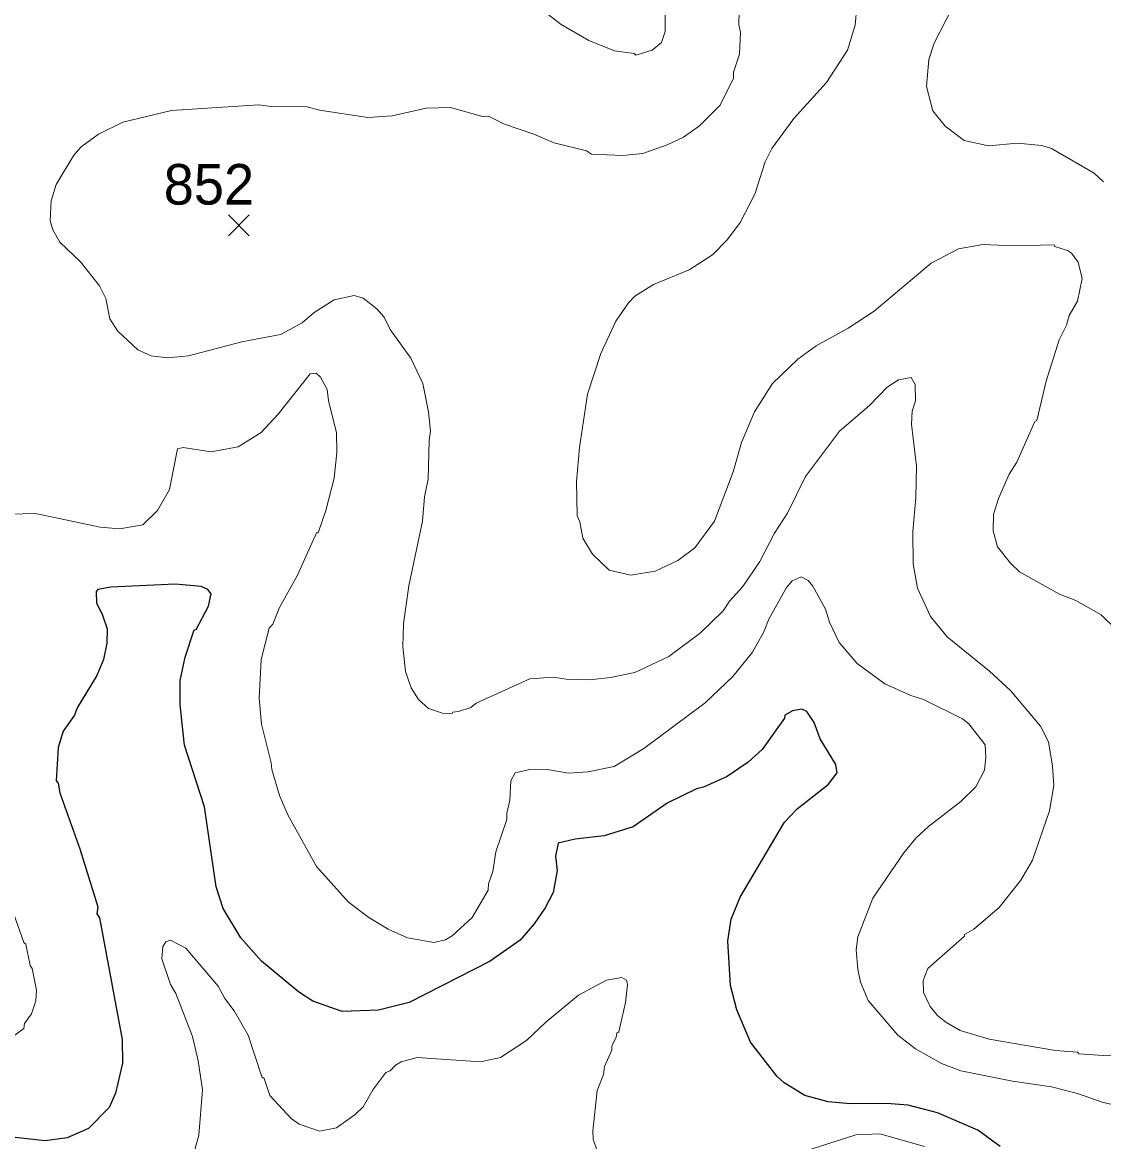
# Model space of a CAD drawing. Extents: x 265.7 to 292.1, y 7676.2 to 7704.2.
# Drawn here: x 273.408 to 275.542, y 7690.238 to 7692.446 of the extents above; entities that cross this region are included whole.
import ezdxf
from ezdxf.enums import TextEntityAlignment as Align

# ---------------------------------------------------------------- set-up
doc = ezdxf.new("R2010")
doc.units = 0
doc.header["$LTSCALE"] = 0.032
for name, color, linetype, lineweight in [('1', 7, 'Continuous', 25), ('2', 7, 'Continuous', 13), ('21', 7, 'Continuous', 25)]:
    doc.layers.add(name, color=color, linetype=linetype, lineweight=lineweight)
doc.layers.add('61', color=7, linetype='Continuous')

msp = doc.modelspace()

# ---------------------------------------------------------------- linework, layer by layer
at = {"layer": '1'}
for points in [[(275.3375, 7690.2284), (275.2936, 7690.2603), (275.2138, 7690.2946), (275.1564, 7690.3098), (275.1133, 7690.313), (275.0415, 7690.3122), (274.9984, 7690.3162), (274.9521, 7690.3289), (274.9114, 7690.3537), (274.8978, 7690.3664), (274.8451, 7690.4343), (274.818, 7690.4981), (274.8053, 7690.546), (274.8005, 7690.6338), (274.8068, 7690.6768), (274.8244, 7690.7199), (274.9122, 7690.8684), (274.9369, 7690.8947), (274.9984, 7690.9426), (275.0159, 7690.9657), (275.0135, 7690.9817), (274.9824, 7691.0327), (274.9704, 7691.0647), (274.9561, 7691.0862), (274.9465, 7691.091), (274.9281, 7691.0878), (274.913, 7691.079), (274.9122, 7691.0734), (274.8683, 7691.0112), (274.8404, 7690.9864), (274.7989, 7690.9585), (274.7526, 7690.937), (274.7382, 7690.9338), (274.6808, 7690.9058), (274.6138, 7690.8588), (274.5563, 7690.8412), (274.4988, 7690.8348), (274.4653, 7690.8268), (274.4605, 7690.8013), (274.4637, 7690.7726), (274.4557, 7690.7295), (274.4398, 7690.6992), (274.4182, 7690.6673), (274.3903, 7690.6353), (274.3313, 7690.5938), (274.1717, 7690.5125), (274.111, 7690.4973), (274.0392, 7690.4949), (273.9818, 7690.5148), (273.953, 7690.5332), (273.8804, 7690.5938), (273.8397, 7690.6401), (273.8046, 7690.6976), (273.791, 7690.7407), (273.7679, 7690.8987), (273.728, 7691.02), (273.72, 7691.0998), (273.72, 7691.1476), (273.7296, 7691.1939), (273.7472, 7691.2474), (273.7511, 7691.2482), (273.7759, 7691.2945), (273.7807, 7691.3184), (273.7743, 7691.3272), (273.7615, 7691.3328), (273.7105, 7691.3375), (273.5828, 7691.332), (273.5572, 7691.3272), (273.5541, 7691.3232), (273.5549, 7691.3)], [(273.5549, 7691.3), (273.566, 7691.2785), (273.5756, 7691.2498), (273.5748, 7691.2211), (273.5684, 7691.1891), (273.5556, 7691.1572), (273.5165, 7691.0934)], [(273.5165, 7691.0934), (273.511, 7691.079), (273.4886, 7691.0479), (273.479, 7691.0152), (273.4751, 7690.9497), (273.479, 7690.945), (273.4822, 7690.9258), (273.5221, 7690.8157), (273.5572, 7690.7008), (273.5556, 7690.6872), (273.5604, 7690.6792), (273.6051, 7690.4391), (273.6059, 7690.3928), (273.5923, 7690.3337), (273.5796, 7690.305), (273.5389, 7690.2635), (273.4966, 7690.2451), (273.4535, 7690.2395), (273.3099, 7690.2555)]]:
    msp.add_lwpolyline(points, dxfattribs=at)
at = {"layer": '2'}
for points in [[(274.6768, 7692.4659), (274.6768, 7692.4276), (274.6696, 7692.406), (274.6513, 7692.3909), (274.6185, 7692.3813), (274.6153, 7692.3845), (274.577, 7692.3901), (274.526, 7692.41), (274.4717, 7692.4419), (274.3265, 7692.5536)], [(274.8228, 7692.4675), (274.822, 7692.4419), (274.8252, 7692.426), (274.8236, 7692.3829), (274.8116, 7692.3478), (274.8116, 7692.3358), (274.7853, 7692.2823), (274.7446, 7692.2416), (274.7127, 7692.2193), (274.6808, 7692.2041), (274.6329, 7692.1874), (274.593, 7692.1834), (274.5316, 7692.1858), (274.5212, 7692.1922), (274.4574, 7692.2081), (274.4175, 7692.2257), (274.36, 7692.2448), (274.3281, 7692.2608), (274.3161, 7692.26), (274.2531, 7692.2783), (274.2052, 7692.2768), (274.1382, 7692.2616), (274.0903, 7692.2584), (273.9945, 7692.2728), (273.9706, 7692.2791), (273.8988, 7692.2799), (273.8748, 7692.2831), (273.7025, 7692.272), (273.6067, 7692.2488), (273.5588, 7692.2257), (273.5245, 7692.2001), (273.5102, 7692.1842), (273.4751, 7692.1259), (273.4655, 7692.094), (273.4631, 7692.0541), (273.4687, 7692.0366), (273.4822, 7692.0126), (273.5229, 7691.9735), (273.5604, 7691.9264), (273.5732, 7691.9009), (273.5812, 7691.861), (273.5963, 7691.8371), (273.6362, 7691.7996), (273.6626, 7691.7884), (273.6945, 7691.7844), (273.736, 7691.7884), (273.8413, 7691.8155), (273.9179, 7691.8299), (273.9602, 7691.853), (273.9842, 7691.8738)], [(275.055, 7692.477), (275.0518, 7692.4403), (275.0367, 7692.3909), (274.9952, 7692.327), (274.9305, 7692.256), (274.8874, 7692.197), (274.8739, 7692.1706), (274.8539, 7692.1068), (274.8244, 7692.0509), (274.7997, 7692.0174), (274.7701, 7691.9871), (274.7239, 7691.9576), (274.6537, 7691.9288), (274.6169, 7691.9057), (274.6042, 7691.8929), (274.5794, 7691.8562), (274.5499, 7691.7924), (274.5236, 7691.7126), (274.5076, 7691.6073), (274.502, 7691.5402), (274.5028, 7691.4724), (274.5084, 7691.4604), (274.514, 7691.4285), (274.5332, 7691.3966), (274.5659, 7691.3655), (274.609, 7691.3551), (274.6568, 7691.3631), (274.7015, 7691.3846), (274.735, 7691.4094), (274.7741, 7691.462), (274.8108, 7691.5594), (274.8276, 7691.6168), (274.8531, 7691.6775), (274.8882, 7691.7333), (274.9385, 7691.7812), (274.9744, 7691.8076), (275.0375, 7691.8427), (275.0893, 7691.8762), (275.2018, 7691.9711), (275.2553, 7691.9991), (275.3032, 7692.0078), (275.3638, 7692.0054), (275.4444, 7692.007), (275.4452, 7692.0038), (275.4708, 7691.9959), (275.4787, 7691.9903), (275.4915, 7691.9727), (275.4995, 7691.9408), (275.4899, 7691.8961), (275.4739, 7691.8674), (275.4684, 7691.8483), (275.454, 7691.8195), (275.4285, 7691.7381), (275.4101, 7691.6607), (275.4061, 7691.6583), (275.3702, 7691.5785)], [(275.2433, 7692.4754), (275.2074, 7692.4052), (275.1971, 7692.3725), (275.1923, 7692.3191), (275.205, 7692.2712), (275.229, 7692.2409), (275.2665, 7692.2129), (275.3144, 7692.2025), (275.3718, 7692.2073), (275.4197, 7692.2033), (275.4388, 7692.197), (275.5234, 7692.1483), (275.5418, 7692.1315)], [(273.9842, 7691.8738), (274.0233, 7691.8985), (274.0632, 7691.9073), (274.0807, 7691.9017), (274.1078, 7691.881), (274.1222, 7691.8642), (274.1342, 7691.8403)], [(274.1342, 7691.8403), (274.1749, 7691.7836), (274.1988, 7691.7333), (274.21, 7691.6775), (274.214, 7691.6392), (274.2108, 7691.6216), (274.2092, 7691.545), (274.202, 7691.5099), (274.198, 7691.462), (274.1709, 7691.3344), (274.1605, 7691.2594), (274.1589, 7691.2147), (274.1645, 7691.1652), (274.1757, 7691.1333), (274.19, 7691.1101), (274.21, 7691.0926), (274.2371, 7691.083), (274.2563, 7691.0822), (274.2571, 7691.0854), (274.269, 7691.0862), (274.293, 7691.0942), (274.3041, 7691.103), (274.4095, 7691.1508), (274.4558, 7691.154), (274.4813, 7691.15), (274.5276, 7691.1492), (274.5691, 7691.1532), (274.6169, 7691.1636), (274.684, 7691.1947), (274.7462, 7691.2418), (274.7909, 7691.2849), (274.8037, 7691.304), (274.83, 7691.3328), (274.8635, 7691.3822), (274.8922, 7691.4381), (274.9178, 7691.478), (274.9537, 7691.5498), (275.0207, 7691.6392), (275.0798, 7691.6903), (275.1149, 7691.7262), (275.1372, 7691.7405), (275.162, 7691.7453), (275.1699, 7691.7318), (275.1707, 7691.699), (275.1643, 7691.6791), (275.1627, 7691.6536), (275.1723, 7691.5706), (275.1715, 7691.5083), (275.1651, 7691.4413), (275.1659, 7691.3775), (275.1747, 7691.3296), (275.2002, 7691.2737), (275.233, 7691.2338), (275.3168, 7691.166), (275.3582, 7691.1277), (275.4173, 7691.0575), (275.4333, 7691.0264), (275.4412, 7690.9785), (275.4436, 7690.9402), (275.4348, 7690.8907), (275.4013, 7690.7933), (275.3782, 7690.7535), (275.3359, 7690.7), (275.2856, 7690.6569), (275.2673, 7690.6465), (275.2673, 7690.6433), (275.1947, 7690.5795), (275.1859, 7690.5556), (275.1867, 7690.5324), (275.1994, 7690.5045), (275.2138, 7690.4869), (275.2306, 7690.4734), (275.2585, 7690.4574), (275.316, 7690.4398), (275.4468, 7690.4175), (275.4899, 7690.4143), (275.4931, 7690.4111), (275.541, 7690.4079), (275.5889, 7690.4095)], [(273.3849, 7691.4756), (273.4344, 7691.4772), (273.562, 7691.4501), (273.6003, 7691.4469), (273.6458, 7691.4549), (273.6753, 7691.4828), (273.6985, 7691.5243), (273.7144, 7691.6049), (273.7256, 7691.6073), (273.7807, 7691.5985), (273.8341, 7691.6089), (273.8796, 7691.6368), (273.9131, 7691.6727), (273.9762, 7691.7525), (273.9882, 7691.7541), (273.9969, 7691.7461), (274.0097, 7691.7214), (274.0121, 7691.6998), (274.028, 7691.636), (274.0288, 7691.5977), (274.0233, 7691.5466), (274.0073, 7691.4828), (273.9921, 7691.4389), (273.9889, 7691.4389), (273.9514, 7691.3551), (273.9155, 7691.2913), (273.9028, 7691.2585), (273.8956, 7691.2506), (273.8796, 7691.1891), (273.8756, 7691.1125), (273.8804, 7691.0615), (273.8996, 7690.9849), (273.9004, 7690.9721), (273.9155, 7690.921), (273.9323, 7690.8827), (273.9889, 7690.7806), (274.052, 7690.7104), (274.0919, 7690.68), (274.1302, 7690.6569), (274.1685, 7690.6401), (274.2204, 7690.6306), (274.2435, 7690.6361), (274.2563, 7690.6441), (274.2962, 7690.68), (274.3273, 7690.7343), (274.3281, 7690.7463), (274.3369, 7690.771), (274.3424, 7690.8093), (274.364, 7690.8731), (274.364, 7690.8859)], [(275.3702, 7691.5785), (275.3551, 7691.5546), (275.3343, 7691.5067), (275.3247, 7691.4748), (275.3239, 7691.4429), (275.3327, 7691.411), (275.3582, 7691.379)], [(275.3582, 7691.379), (275.3758, 7691.3623), (275.4548, 7691.3176), (275.4867, 7691.3056), (275.537, 7691.2769), (275.5657, 7691.249)], [(274.4861, 7690.9649), (274.5244, 7690.9673), (274.5762, 7690.9777), (274.6345, 7691.0136), (274.7558, 7691.1037), (274.81, 7691.1556), (274.8491, 7691.2035), (274.8715, 7691.2434), (274.8811, 7691.2689), (274.9162, 7691.3312), (274.9273, 7691.3439), (274.9449, 7691.3519), (274.9585, 7691.3447), (274.968, 7691.3336), (274.9928, 7691.2881), (275.0008, 7691.2625), (275.0199, 7691.2227), (275.0558, 7691.1812), (275.1101, 7691.1413), (275.1612, 7691.1181), (275.1867, 7691.1101), (275.2633, 7691.0718), (275.2761, 7691.0623), (275.308, 7691.0208), (275.3096, 7690.996), (275.3064, 7690.9705), (275.2896, 7690.9378), (275.2601, 7690.909), (275.1963, 7690.8596), (275.1715, 7690.8364), (275.1476, 7690.8077), (275.0861, 7690.7183), (275.0566, 7690.6417), (275.0534, 7690.6162), (275.0566, 7690.5779), (275.0622, 7690.5524), (275.0774, 7690.5164), (275.1356, 7690.4478), (275.1707, 7690.4207), (275.2218, 7690.392), (275.2601, 7690.3776), (275.3622, 7690.3569), (275.4388, 7690.3457), (275.4899, 7690.3329), (275.541, 7690.3154), (275.5921, 7690.3042)], [(274.364, 7690.8859), (274.3704, 7690.9114), (274.372, 7690.9497), (274.3807, 7690.9657), (274.4095, 7690.9721), (274.4478, 7690.9713), (274.4861, 7690.9649)], [(273.3625, 7690.4255), (273.4112, 7690.4614), (273.4128, 7690.471), (273.4264, 7690.4901), (273.4352, 7690.5157), (273.436, 7690.5364), (273.428, 7690.5795), (273.424, 7690.5851), (273.4152, 7690.6274), (273.4112, 7690.6306), (273.3849, 7690.7056)], [(273.7368, 7690.1789), (273.7567, 7690.2507), (273.7639, 7690.3401), (273.7551, 7690.3976), (273.744, 7690.4454), (273.7113, 7690.53), (273.7009, 7690.5476), (273.6833, 7690.5986), (273.6857, 7690.6226), (273.6913, 7690.6322), (273.7009, 7690.6353), (273.7312, 7690.6194), (273.795, 7690.5444), (273.8078, 7690.5204), (273.8262, 7690.4957), (273.8541, 7690.4478), (273.8812, 7690.3656), (273.8852, 7690.3624), (273.8964, 7690.3289), (273.9387, 7690.2834), (273.9546, 7690.2723), (273.9945, 7690.2587), (274.028, 7690.2651), (274.0648, 7690.2914), (274.0807, 7690.3066), (274.0999, 7690.3401), (274.1254, 7690.3744), (274.1342, 7690.3776), (274.1445, 7690.3888)], [(274.4414, 7690.4734), (274.506, 7690.5268), (274.5611, 7690.5563), (274.5914, 7690.5619), (274.6002, 7690.5563), (274.6026, 7690.5476), (274.5986, 7690.5125), (274.585, 7690.4542), (274.581, 7690.4518), (274.5802, 7690.4438), (274.5715, 7690.4263), (274.5715, 7690.4183), (274.5571, 7690.3864), (274.5547, 7690.3704), (274.5427, 7690.3385), (274.5339, 7690.2587), (274.5347, 7690.2428), (274.5435, 7690.2156)], [(274.1445, 7690.3888), (274.1557, 7690.3952), (274.1876, 7690.4039), (274.3121, 7690.3952), (274.352, 7690.4039), (274.4031, 7690.4374), (274.4414, 7690.4734)], [(274.9649, 7690.2228), (275.0526, 7690.2515), (275.1005, 7690.2531), (275.1883, 7690.2284)]]:
    msp.add_lwpolyline(points, dxfattribs=at)
at = {"layer": '21'}
for p, q in [((273.815, 7692.0663), (273.8562, 7692.0251)), ((273.8562, 7692.0663), (273.815, 7692.0251))]:
    msp.add_line(p, q, dxfattribs=at)

# ---------------------------------------------------------------- texts
at = {"layer": '61'}
msp.add_text('852', height=0.08, dxfattribs=at).set_placement((273.7765, 7692.0865), align=Align.CENTER)

doc.saveas('drawing.dxf')
